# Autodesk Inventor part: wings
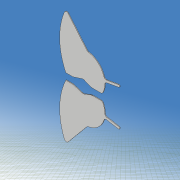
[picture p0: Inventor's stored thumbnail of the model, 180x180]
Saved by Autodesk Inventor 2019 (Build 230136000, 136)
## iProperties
Created: 2021-05
Part Number: wings
Material: 一般
Document SubType Name: Modeling
Designer: kikut
Density: 1 g/cm^3
Appearance: 既定
Author: kikut
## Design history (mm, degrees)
sketch "スケッチ1"
  geometry: L1 (80, 60)-(-80, 60); L2 (-80, 60)-(-80, -60); L3 (-80, -60)-(80, -60); L4 (80, -60)-(80, 60); L5 (80, 60)-(-80, -60); L6 (-80, 60)-(80, -60); 1 further point
  constraints: 12 end point, 2 midpoint, 2 parallel, 1 horizontal, 1 perpendicular
  dimensions: "d0" = 160 distance of L2.end L3.end; "d1" = 120 distance of L1.end L2.end
extrude "押し出し1" new body sketch "スケッチ1" stored distance "d2" = 0.6; taper "d3" = 0 deg
sketch "スケッチ2"
  geometry: L1 (-140, 0)-(140, 0) reference; L2 (0, -54)-(20, -30); L3 (0, 54)-(20, 30); L4 (0, -3)-(6.514, -3); L5 (6.514, -3)-(16, -6); L6 (16, -6)-(24, -3); L7 (24, -3)-(33.716, -3); L8 (0, 3)-(6.514, 3); L9 (6.514, 3)-(16, 6); L10 (16, 6)-(24, 3); L11 (24, 3)-(33.716, 3); L12 (0, -98)-(0, 98) reference; L13 (-100, -70)-(100, -70); L14 (100, -70)-(100, 70); L15 (100, 70)-(-100, 70); L16 (-100, 70)-(-100, -70); L17 (-100, -70)-(100, 70); L18 (100, -70)-(-100, 70); A1 r 60 centre (54.312, 28.5) between (0, 54) and (0, 3); A2 r 60 centre (54.312, -28.5) between (0, -3) and (0, -54); A3 r 18.111 centre (18, -12) between (20, -30) and (33.716, -3); A4 r 18.111 centre (18, 12) between (33.716, 3) and (20, 30); 1 further point
  constraints: 32 end point, 8 point on circle, 8 symmetric about line, 4 centre point, 3 horizontal, 2 collinear, 2 midpoint, 2 parallel, 1 perpendicular
  dimensions: "d5" = 60 radius of A1; "d6" = 6 distance of L8.start L4.start; "d7" = 108 distance of L3.start L2.start; "d8" = 0 horizontal distance of L3.start L8.start; "d9" = 60 distance of L3.end L2.end; "d10" = 0 horizontal distance of point (0, 0) L3.start; "d11" = 20 horizontal distance of L3.start L3.end; "d12" = 24 distance of A4.centre A3.centre; "d13" = 6 distance of L11.end L7.end; "d14" = 12 distance of L9.end L5.end; "d15" = 16 distance from line of L12 L5.end; "d16" = 24 distance from line of L6.end L12; "d17" = 200 distance of L14.end L15.end; "d18" = 140 distance of L15.end L13.start; "d30" = 18 distance from line of L12 A4.centre
extrude "押し出し2" cut sketch "スケッチ2" stored distance "d19" = 10; taper "d20" = 0 deg
sketch "スケッチ3"
  geometry: L1 (49.705, -17.97)-(33.948, -15.191); L2 (33.948, -15.191)-(34.295, -13.222); L3 (34.295, -13.222)-(50.052, -16); L4 (50.052, -16)-(49.705, -17.97); L5 (49.705, -17.97)-(34.295, -13.222); L6 (33.948, -15.191)-(50.052, -16); L7 (50.052, 16)-(34.295, 13.222); L8 (34.295, 13.222)-(33.948, 15.191); L9 (33.948, 15.191)-(49.705, 17.97); L10 (49.705, 17.97)-(50.052, 16); L11 (50.052, 16)-(33.948, 15.191); L12 (34.295, 13.222)-(49.705, 17.97); L13 (-112, 0)-(112, 0) reference; L14 (0, -84)-(0, 84) reference; 3 further points
  constraints: 24 end point, 4 midpoint, 4 parallel, 2 perpendicular, 2 symmetric about line
  dimensions: "d21" = 2 distance of L3.end L1.start; "d22" = 2 distance of L9.end L7.start; "d23" = 16 distance of L8.end L9.end; "d24" = 42 distance from line of L14 point (42, 15.596); "d26" = 10 deg angle of L7 L13; "d62" = 16 distance from line of L3.end L13
extrude "押し出し3" join sketch "スケッチ3" distance "d27" = 0.6; taper "d28" = 0 deg
fillet "フィレット1" dims "d31" = 2
fillet "フィレット2" dims "d32" = 1
node "ソリッド1"
